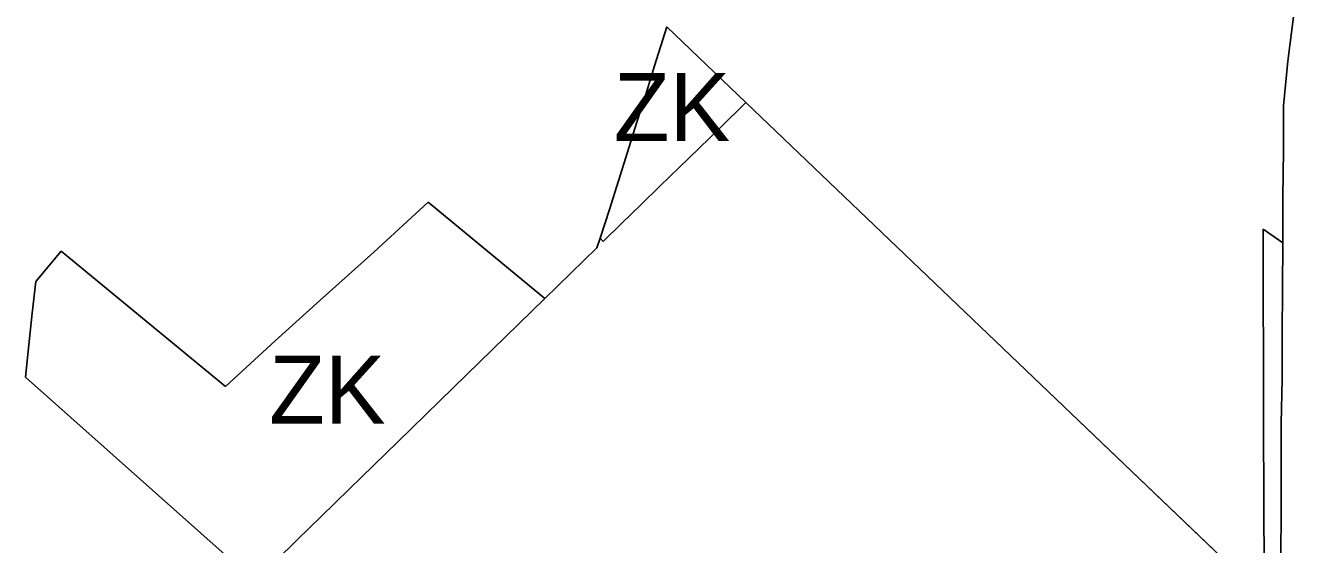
# Model space of a CAD drawing. Extents: x -555509 to -553005, y -1186756 to -1182560.
# Drawn here: x -554520.8 to -554260.1, y -1183086.1 to -1182979.3 of the extents above; entities that cross this region are included whole.
import ezdxf

# ---------------------------------------------------------------- set-up
doc = ezdxf.new("R2010")
doc.units = 0
for name, color, linetype in [('Level 26', 7, 'Continuous'), ('Level 59', 7, 'Continuous'), ('OBRYS_PLOCH', 7, 'Continuous'), ('stav_AP', 7, 'Continuous'), ('stav_LU', 7, 'Continuous'), ('stav_ZK', 7, 'Continuous')]:
    doc.layers.add(name, color=color, linetype=linetype)

msp = doc.modelspace()

# ---------------------------------------------------------------- linework, layer by layer
at = {"layer": 'Level 26'}
for p, q in [((-554262.38, -1183024.08), (-554266.38, -1183021.27)), ((-554266.38, -1183021.27), (-554266.32, -1183061.49)), ((-554262.41, -1183033.48), (-554262.38, -1183024.08)), ((-554262.48, -1183042.92), (-554262.41, -1183033.48)), ((-554262.51, -1183052.04), (-554262.48, -1183042.92)), ((-554262.68, -1183061.22), (-554262.51, -1183052.04)), ((-554266.32, -1183061.49), (-554266.18, -1183097.12)), ((-554262.7, -1183070.3), (-554262.68, -1183061.22)), ((-554262.73, -1183079.38), (-554262.7, -1183070.3)), ((-554262.78, -1183088.46), (-554262.73, -1183079.38))]:
    msp.add_line(p, q, dxfattribs=at)
at = {"layer": 'OBRYS_PLOCH'}
for p, q in [((-554261.3, -1182986.71), (-554260.14, -1182977.6)), ((-554260.14, -1182977.6), (-554261.3, -1182986.71)), ((-554388.93, -1182979.65), (-554391.47, -1182987.64)), ((-554391.47, -1182987.64), (-554388.93, -1182979.65)), ((-554372.68, -1182995.2), (-554388.93, -1182979.65)), ((-554388.93, -1182979.65), (-554372.68, -1182995.2)), ((-554391.47, -1182987.64), (-554393.27, -1182993.57)), ((-554393.27, -1182993.57), (-554391.47, -1182987.64)), ((-554262.22, -1182995.89), (-554261.3, -1182986.71)), ((-554261.3, -1182986.71), (-554262.22, -1182995.89)), ((-554393.27, -1182993.57), (-554395.17, -1182999.46)), ((-554395.17, -1182999.46), (-554393.27, -1182993.57)), ((-554378.08, -1183000.47), (-554372.68, -1182995.2)), ((-554372.68, -1182995.2), (-554378.08, -1183000.47)), ((-554372.68, -1182995.2), (-554316.77, -1183048.71)), ((-554316.77, -1183048.71), (-554372.68, -1182995.2)), ((-554262.21, -1183005.1), (-554262.22, -1182995.89)), ((-554262.22, -1182995.89), (-554262.21, -1183005.1)), ((-554395.17, -1182999.46), (-554397, -1183005.38)), ((-554397, -1183005.38), (-554395.17, -1182999.46)), ((-554382.31, -1183004.59), (-554378.08, -1183000.47)), ((-554378.08, -1183000.47), (-554382.31, -1183004.59)), ((-554397, -1183005.38), (-554398.87, -1183011.31)), ((-554398.87, -1183011.31), (-554397, -1183005.38)), ((-554386.38, -1183008.56), (-554382.31, -1183004.59)), ((-554382.31, -1183004.59), (-554386.38, -1183008.56)), ((-554262.33, -1183014.59), (-554262.21, -1183005.1)), ((-554262.21, -1183005.1), (-554262.33, -1183014.59)), ((-554390.36, -1183012.44), (-554386.38, -1183008.56)), ((-554386.38, -1183008.56), (-554390.36, -1183012.44)), ((-554398.87, -1183011.31), (-554400.71, -1183017.23)), ((-554400.71, -1183017.23), (-554398.87, -1183011.31)), ((-554394.29, -1183016.28), (-554390.36, -1183012.44)), ((-554390.36, -1183012.44), (-554394.29, -1183016.28)), ((-554437.96, -1183015.71), (-554449.17, -1183025.95)), ((-554449.17, -1183025.95), (-554437.96, -1183015.71)), ((-554413.98, -1183035.48), (-554437.96, -1183015.71)), ((-554437.96, -1183015.71), (-554413.98, -1183035.48)), ((-554398.16, -1183020.05), (-554394.29, -1183016.28)), ((-554394.29, -1183016.28), (-554398.16, -1183020.05)), ((-554262.38, -1183024.08), (-554262.33, -1183014.59)), ((-554262.33, -1183014.59), (-554262.38, -1183024.08)), ((-554400.71, -1183017.23), (-554402.67, -1183023.1)), ((-554402.67, -1183023.1), (-554400.71, -1183017.23)), ((-554402.03, -1183023.82), (-554398.16, -1183020.05)), ((-554398.16, -1183020.05), (-554402.03, -1183023.82)), ((-554266.32, -1183061.49), (-554266.38, -1183021.27)), ((-554266.38, -1183021.27), (-554262.38, -1183024.08)), ((-554262.38, -1183024.08), (-554266.38, -1183021.27)), ((-554266.38, -1183021.27), (-554266.32, -1183061.49)), ((-554403.33, -1183025.09), (-554402.67, -1183023.1)), ((-554402.67, -1183023.1), (-554403.33, -1183025.09)), ((-554402.67, -1183023.1), (-554402.03, -1183023.82)), ((-554402.03, -1183023.82), (-554402.67, -1183023.1)), ((-554262.41, -1183033.48), (-554262.38, -1183024.08)), ((-554262.38, -1183024.08), (-554262.41, -1183033.48)), ((-554513.4, -1183025.76), (-554518.6, -1183032.04)), ((-554518.6, -1183032.04), (-554513.4, -1183025.76)), ((-554479.62, -1183053.63), (-554513.4, -1183025.76)), ((-554513.4, -1183025.76), (-554479.62, -1183053.63)), ((-554449.17, -1183025.95), (-554460.24, -1183035.89)), ((-554460.24, -1183035.89), (-554449.17, -1183025.95)), ((-554413.98, -1183035.48), (-554403.33, -1183025.09)), ((-554403.33, -1183025.09), (-554413.98, -1183035.48)), ((-554518.6, -1183032.04), (-554519.39, -1183038.52)), ((-554519.39, -1183038.52), (-554518.6, -1183032.04)), ((-554262.48, -1183042.92), (-554262.41, -1183033.48)), ((-554262.41, -1183033.48), (-554262.48, -1183042.92)), ((-554460.24, -1183035.89), (-554469.42, -1183044.22)), ((-554469.42, -1183044.22), (-554460.24, -1183035.89)), ((-554424.78, -1183046.02), (-554413.98, -1183035.48)), ((-554413.98, -1183035.48), (-554424.78, -1183046.02)), ((-554519.39, -1183038.52), (-554520.07, -1183045.01)), ((-554520.07, -1183045.01), (-554519.39, -1183038.52)), ((-554520.07, -1183045.01), (-554520.76, -1183051.66)), ((-554520.76, -1183051.66), (-554520.07, -1183045.01)), ((-554469.42, -1183044.22), (-554479.62, -1183053.63)), ((-554479.62, -1183053.63), (-554469.42, -1183044.22)), ((-554262.51, -1183052.04), (-554262.48, -1183042.92)), ((-554262.48, -1183042.92), (-554262.51, -1183052.04)), ((-554435.56, -1183056.53), (-554424.78, -1183046.02)), ((-554424.78, -1183046.02), (-554435.56, -1183056.53)), ((-554316.77, -1183048.71), (-554266.18, -1183097.12)), ((-554276.49, -1183087.26), (-554316.77, -1183048.71)), ((-554520.76, -1183051.66), (-554473.59, -1183093.62)), ((-554473.59, -1183093.62), (-554520.76, -1183051.66)), ((-554262.68, -1183061.22), (-554262.51, -1183052.04)), ((-554262.51, -1183052.04), (-554262.68, -1183061.22)), ((-554444.23, -1183064.98), (-554435.56, -1183056.53)), ((-554435.56, -1183056.53), (-554444.23, -1183064.98)), ((-554266.18, -1183097.12), (-554266.32, -1183061.49)), ((-554266.32, -1183061.49), (-554266.18, -1183097.12)), ((-554262.7, -1183070.3), (-554262.68, -1183061.22)), ((-554262.68, -1183061.22), (-554262.7, -1183070.3)), ((-554454.14, -1183074.65), (-554444.23, -1183064.98)), ((-554444.23, -1183064.98), (-554454.14, -1183074.65)), ((-554262.73, -1183079.38), (-554262.7, -1183070.3)), ((-554262.7, -1183070.3), (-554262.73, -1183079.38)), ((-554460.03, -1183080.39), (-554454.14, -1183074.65)), ((-554454.14, -1183074.65), (-554460.03, -1183080.39)), ((-554464.78, -1183085.02), (-554460.03, -1183080.39)), ((-554460.03, -1183080.39), (-554464.78, -1183085.02)), ((-554262.78, -1183088.46), (-554262.73, -1183079.38)), ((-554262.73, -1183079.38), (-554262.78, -1183088.46)), ((-554469.46, -1183089.59), (-554464.78, -1183085.02)), ((-554464.78, -1183085.02), (-554469.46, -1183089.59))]:
    msp.add_line(p, q, dxfattribs=at)
at = {"layer": 'stav_AP'}
for p, q in [((-554260.14, -1182977.6), (-554261.3, -1182986.71)), ((-554261.3, -1182986.71), (-554262.22, -1182995.89)), ((-554372.68, -1182995.2), (-554378.08, -1183000.47)), ((-554316.77, -1183048.71), (-554372.68, -1182995.2)), ((-554262.22, -1182995.89), (-554262.21, -1183005.1)), ((-554378.08, -1183000.47), (-554382.31, -1183004.59)), ((-554382.31, -1183004.59), (-554386.38, -1183008.56)), ((-554262.21, -1183005.1), (-554262.33, -1183014.59)), ((-554386.38, -1183008.56), (-554390.36, -1183012.44)), ((-554390.36, -1183012.44), (-554394.29, -1183016.28)), ((-554394.29, -1183016.28), (-554398.16, -1183020.05)), ((-554262.33, -1183014.59), (-554262.38, -1183024.08)), ((-554398.16, -1183020.05), (-554402.03, -1183023.82)), ((-554402.67, -1183023.1), (-554403.33, -1183025.09)), ((-554402.03, -1183023.82), (-554402.67, -1183023.1)), ((-554262.38, -1183024.08), (-554262.41, -1183033.48)), ((-554403.33, -1183025.09), (-554413.98, -1183035.48)), ((-554262.41, -1183033.48), (-554262.48, -1183042.92)), ((-554413.98, -1183035.48), (-554424.78, -1183046.02)), ((-554262.48, -1183042.92), (-554262.51, -1183052.04)), ((-554424.78, -1183046.02), (-554435.56, -1183056.53)), ((-554276.49, -1183087.26), (-554316.77, -1183048.71)), ((-554262.51, -1183052.04), (-554262.68, -1183061.22)), ((-554435.56, -1183056.53), (-554444.23, -1183064.98)), ((-554262.68, -1183061.22), (-554262.7, -1183070.3)), ((-554444.23, -1183064.98), (-554454.14, -1183074.65)), ((-554262.7, -1183070.3), (-554262.73, -1183079.38)), ((-554454.14, -1183074.65), (-554460.03, -1183080.39)), ((-554460.03, -1183080.39), (-554464.78, -1183085.02)), ((-554262.73, -1183079.38), (-554262.78, -1183088.46)), ((-554464.78, -1183085.02), (-554469.46, -1183089.59))]:
    msp.add_line(p, q, dxfattribs=at)
at = {"layer": 'stav_LU'}
for p, q in [((-554261.3, -1182986.71), (-554260.14, -1182977.6)), ((-554391.47, -1182987.64), (-554388.93, -1182979.65)), ((-554388.93, -1182979.65), (-554372.68, -1182995.2)), ((-554393.27, -1182993.57), (-554391.47, -1182987.64)), ((-554262.22, -1182995.89), (-554261.3, -1182986.71)), ((-554395.17, -1182999.46), (-554393.27, -1182993.57)), ((-554372.68, -1182995.2), (-554316.77, -1183048.71)), ((-554262.21, -1183005.1), (-554262.22, -1182995.89)), ((-554397, -1183005.38), (-554395.17, -1182999.46)), ((-554398.87, -1183011.31), (-554397, -1183005.38)), ((-554262.33, -1183014.59), (-554262.21, -1183005.1)), ((-554400.71, -1183017.23), (-554398.87, -1183011.31)), ((-554449.17, -1183025.95), (-554437.96, -1183015.71)), ((-554437.96, -1183015.71), (-554413.98, -1183035.48)), ((-554262.38, -1183024.08), (-554262.33, -1183014.59)), ((-554402.67, -1183023.1), (-554400.71, -1183017.23)), ((-554266.32, -1183061.49), (-554266.38, -1183021.27)), ((-554266.38, -1183021.27), (-554262.38, -1183024.08)), ((-554403.33, -1183025.09), (-554402.67, -1183023.1)), ((-554518.6, -1183032.04), (-554513.4, -1183025.76)), ((-554513.4, -1183025.76), (-554479.62, -1183053.63)), ((-554460.24, -1183035.89), (-554449.17, -1183025.95)), ((-554413.98, -1183035.48), (-554403.33, -1183025.09)), ((-554519.39, -1183038.52), (-554518.6, -1183032.04)), ((-554469.42, -1183044.22), (-554460.24, -1183035.89)), ((-554520.07, -1183045.01), (-554519.39, -1183038.52)), ((-554520.76, -1183051.66), (-554520.07, -1183045.01)), ((-554479.62, -1183053.63), (-554469.42, -1183044.22)), ((-554316.77, -1183048.71), (-554266.18, -1183097.12)), ((-554473.59, -1183093.62), (-554520.76, -1183051.66)), ((-554266.18, -1183097.12), (-554266.32, -1183061.49))]:
    msp.add_line(p, q, dxfattribs=at)
at = {"layer": 'stav_ZK'}
for p, q in [((-554388.93, -1182979.65), (-554391.47, -1182987.64)), ((-554372.68, -1182995.2), (-554388.93, -1182979.65)), ((-554391.47, -1182987.64), (-554393.27, -1182993.57)), ((-554393.27, -1182993.57), (-554395.17, -1182999.46)), ((-554378.08, -1183000.47), (-554372.68, -1182995.2)), ((-554395.17, -1182999.46), (-554397, -1183005.38)), ((-554382.31, -1183004.59), (-554378.08, -1183000.47)), ((-554397, -1183005.38), (-554398.87, -1183011.31)), ((-554386.38, -1183008.56), (-554382.31, -1183004.59)), ((-554390.36, -1183012.44), (-554386.38, -1183008.56)), ((-554398.87, -1183011.31), (-554400.71, -1183017.23)), ((-554394.29, -1183016.28), (-554390.36, -1183012.44)), ((-554437.96, -1183015.71), (-554449.17, -1183025.95)), ((-554413.98, -1183035.48), (-554437.96, -1183015.71)), ((-554398.16, -1183020.05), (-554394.29, -1183016.28)), ((-554400.71, -1183017.23), (-554402.67, -1183023.1)), ((-554402.03, -1183023.82), (-554398.16, -1183020.05)), ((-554402.67, -1183023.1), (-554402.03, -1183023.82)), ((-554513.4, -1183025.76), (-554518.6, -1183032.04)), ((-554479.62, -1183053.63), (-554513.4, -1183025.76)), ((-554449.17, -1183025.95), (-554460.24, -1183035.89)), ((-554518.6, -1183032.04), (-554519.39, -1183038.52)), ((-554460.24, -1183035.89), (-554469.42, -1183044.22)), ((-554424.78, -1183046.02), (-554413.98, -1183035.48)), ((-554519.39, -1183038.52), (-554520.07, -1183045.01)), ((-554520.07, -1183045.01), (-554520.76, -1183051.66)), ((-554469.42, -1183044.22), (-554479.62, -1183053.63)), ((-554435.56, -1183056.53), (-554424.78, -1183046.02)), ((-554520.76, -1183051.66), (-554473.59, -1183093.62)), ((-554444.23, -1183064.98), (-554435.56, -1183056.53)), ((-554454.14, -1183074.65), (-554444.23, -1183064.98)), ((-554460.03, -1183080.39), (-554454.14, -1183074.65)), ((-554464.78, -1183085.02), (-554460.03, -1183080.39)), ((-554469.46, -1183089.59), (-554464.78, -1183085.02))]:
    msp.add_line(p, q, dxfattribs=at)

# ---------------------------------------------------------------- texts
at = {"layer": 'Level 59'}
for p in [(-554399.83, -1183003.14), (-554470.67, -1183061.26)]:
    msp.add_text('ZK', height=14, dxfattribs=at).set_placement(p)

doc.saveas('drawing.dxf')
